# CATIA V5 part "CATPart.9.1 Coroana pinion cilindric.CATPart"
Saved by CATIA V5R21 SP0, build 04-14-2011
Part number: Coroana pinion cilindric
Bounding box of the stored display mesh (mm): x -26.905 to 26.634, y -26.886 to 26.822, z -26 to 126
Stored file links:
  C:\Users\MIRCEA\Desktop\MOM\Mogan\model\CATPart.9.1 Coroana pinion cilindric.CATPart
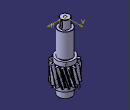
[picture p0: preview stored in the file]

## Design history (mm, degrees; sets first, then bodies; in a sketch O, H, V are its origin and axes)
Parameters
  `Date de intrare` = ""
  z1 = 15
  z2 = 49
  beta = 15 deg
  m_n = 3 mm
  aw = 100 mm
  xn1 = 0.208
  b1 = 40 mm
  b2 = 37 mm
  g = 4 mm
  `Date calculate si limita` = ""
  Ri1 = 16.1677 mm {= rf1-g}
  a = 99.3865 mm {= m_t * (z1 +z2 )/2}
  xn2 = 0.000851888 {= xsn - xn1}
  z1_min = 14
  aw_min = 98.1865 mm {= a - 0.4 * m_n}
  aw_max = 102.3865 mm {= a + m_n}
  x_min = -0.0714286 {= (-z1 + z1_min)/z1_min}
  s_an_min = 1.2 mm {= 0.4*m_n}
  epsilon_affa_min = 1.3
  `Unghiul de rotire` = ""
  ROT_1 = 0 deg
  `Alte date calculate` = ""
  u = 3.26667 {= z2 /z1}
  m_t = 3.1058 mm {= m_n / cos(beta )}
  alfat = 20.6469 deg {= atan(tan(alfa0_n )/cos(beta ))}
  alfawt = 21.5604 deg {= acos(a /aw * cos(alfat ) )}
  xsn = 0.208852 {= (tan(alfawt)-alfawt_r -tan(alfat) + alfat_r) * (z1 +z2 )/tan(alfa0_n)/2}
  aw_rec = 100 mm {= m_t * (z2 +z1 )*cos(alfat )/cos(alfawt )/2}
  rb1 = 21.7976 mm {= rd1 * cos(alfat )}
  rb2 = 71.2055 mm {= rd2 * cos(alfat )}
  rd1 = 23.2937 mm {= m_t *z1/2}
  rd2 = 76.0928 mm {= m_t *z2 /2}
  rw1 = 23.4375 mm {= aw/(u+1)}
  rw2 = 76.5625 mm {= aw-rw1}
  rf1 = 20.1677 mm {= m_n * (z1 /cos(beta )-2*(ha_n +c0_n-xn1 ))/2}
  rf2 = 72.3454 mm {= m_n * (z2 /cos(beta )-2*(ha_n +c0_n-xn2 ))/2}
  ra1 = 26.9046 mm {= (2*aw_rec  -m_n *(z2  /cos(beta )-2*(ha_n -xn2 )))/2}
  ra2 = 79.0823 mm {= (2*aw_rec  -m_n *(z1   /cos(beta )-2*(ha_n -xn1 )))/2}
  `Coordonate ale punctelor de pe evolventa 1` = ""
  Xe11 = 0.0083 mm {= rb1  *sqrt(1+(1*psi_r)  * (1*psi_r) ) * sin((1*phi) - atan((1*psi_r)))}
  Ye11 = 21.9168 mm {= rb1 *sqrt(1+(1*psi_r) * (1*psi_r) ) * cos((1*phi) - atan((1*psi_r )))}
  Xe12 = 0.0665 mm {= rb1  *sqrt(1+(2*psi_r )  * (2*psi_r)) * sin((2*phi) - atan((2*psi_r )))}
  Ye12 = 22.2704 mm {= rb1 *sqrt(1+(2*psi_r) * (2*psi_r) ) * cos((2*phi) - atan((2*psi_r )))}
  Xe13 = 0.2231 mm {= rb1  *sqrt(1+(3*psi_r)  * (3*psi_r) ) * sin((3*phi) - atan((3*psi_r)))}
  Ye13 = 22.8469 mm {= rb1 *sqrt(1+(3*psi_r) * (3*psi_r) ) * cos((3*phi) - atan((3*psi_r )))}
  Xe14 = 0.5247 mm {= rb1*sqrt(1+(4*psi_r)  * (4*psi_r) ) * sin((4*phi) - atan((4*psi_r)))}
  Ye14 = 23.6268 mm {= rb1 *sqrt(1+(4*psi_r) * (4*psi_r) ) * cos((4*phi) - atan((4*psi_r )))}
  Xe15 = 1.0147 mm {= rb1  *sqrt(1+(5*psi_r )  * (5*psi_r)) * sin((5*phi) - atan((5*psi_r )))}
  Ye15 = 24.5839 mm {= rb1 *sqrt(1+(5*psi_r) * (5*psi_r) ) * cos((5*phi) - atan((5*psi_r )))}
  Xe16 = 1.7321 mm {= rb1*sqrt(1+(6*psi_r )  * (6*psi_r)) * sin((6*phi) - atan((6*psi_r )))}
  Ye16 = 25.6848 mm {= rb1 *sqrt(1+(6*psi_r) * (6*psi_r) ) * cos((6*phi) - atan((6*psi_r )))}
  Xe17 = 2.7111 mm {= rb1  *sqrt(1+(7*psi_r )  * (7*psi_r)) * sin((7*phi) - atan((7*psi_r )))}
  Ye17 = 26.8904 mm {= rb1 *sqrt(1+(7*psi_r) * (7*psi_r) ) * cos((7*phi) - atan((7*psi_r )))}
  Xe18 = 3.9797 mm {= rb1  *sqrt(1+(8*psi_r )  * (8*psi_r)) * sin((8*phi) - atan((8*psi_r )))}
  Ye18 = 28.1561 mm {= rb1 *sqrt(1+(8*psi_r) * (8*psi_r) ) * cos((8*phi) - atan((8*psi_r )))}
  tetaC = 1.07882 {= (tan(alfawt ) - alfawt_r )*180/3.14159265}
  tetaC_g = 1.0788 deg {= tetaC *Angle}
  rho = 1.1647 mm {= rho_n *m_t}
  tau1 = 6 deg {= 360/z1 *Angle/4}
  tau2 = 1.8367 deg {= 360/z2 * Angle /4}
  Xe21 = 0.0272 mm {= Xe11 * u}
  Ye21 = 28.4052 mm {= aw_rec - Ye11 * u}
  Xe22 = 0.2171 mm {= Xe12 * u}
  Ye22 = 27.2499 mm {= aw_rec -Ye12 * u}
  Xe23 = 0.7287 mm {= Xe13 * u}
  Ye23 = 25.3669 mm {= aw_rec - Ye13 * u}
  X24 = 1.714 mm {= Xe14 * u}
  Ye24 = 22.8191 mm {= aw_rec -Ye14 * u}
  Xe25 = 3.3146 mm {= Xe15 * u}
  Ye25 = 19.6927 mm {= aw_rec -Ye15 * u}
  Xe26 = 5.6583 mm {= Xe16 * u}
  Ye26 = 16.0962 mm {= aw_rec - Ye16 * u}
  Xe27 = 8.8563 mm {= Xe17 *u}
  Ye27 = 12.1579 mm {= aw_rec -Ye17 * u}
  Xe28 = 13.0004 mm {= Xe18 * u}
  Ye28 = 8.0235 mm {= aw_rec -Ye18 * u}
  rot2 = 0 deg {= - ROT_1/u}
  pbt = 9.1306 mm {= PI * m_t * cos(alfat)}
  phi = 6 deg
  Angle = 1 deg
  alfat_r = 0.360356 {= alfat}
  alfawt_r = 0.376301 {= alfawt}
  psi_r = 0.10472 {= phi}
  `Parametri cremaliera` = ""
  alfa0_n = 20 deg
  ha_n = 1
  c0_n = 0.25
  rho_n = 0.375
  b0 = 1 mm
AxisSystem1: origin (0, 0, 0), X (1, 0, 0), Y (0, 1, 0), Z (0, 0, 1)
Sketch1 on yz-plane, origin (0, 0, 0), H (0, 1, 0), V (0, 0, 1)
  line L1 (16.168, 40) -> (16.168, 0)
  point P4 (0, 66)
  reference projected line E1 through (0, 0) direction (0, 1) from Z axis
  line L2 (16.168, 0) -> (20, 0)
  line L3 (16.168, 40) -> (20, 40)
  line L4 (15, 50) -> (20, 50)
  line L5 (20, 50) -> (20, 40)
  line L6 (20, 0) -> (20, -10)
  line L7 (20, -10) -> (15, -10)
  line L8 (15, -10) -> (15, -26)
  line L9 (15, -26) -> (0, -26)
  point P11 (0, -26)
  line L10 (15, 50) -> (15, 106)
  line L11 (15, 106) -> (10, 106)
  line L12 (10, 106) -> (10, 126)
  line L13 (10, 126) -> (0, 126)
  point P15 (0, 126)
  length L1 = 40
  distance L1 E1 = 16.168
  length L8 = 16
  length L10 = 56
  length L11 = 5
  length L12 = 20
  distance L6 O = 20
  distance L5 V = 20
  vertical: L1 V, L5 V, L6 V, L8 V, L10 V, L12 V
  coincidence: P4 V, P11 V, P15 V
  horizontal: L2 H, L3 H, L4 H, L7 H, L9 H, L11 H, L13 H
Shaft1: profile Sketch1, axis Z axis, angle 360
Set1
  Point1: type OnPlane, Support xy-plane, H 0, V 21.7976 {= rb1}, Direction (1, 0, 0)
  Point2: type OnPlane, Support xy-plane, H 0.0083 {= Xe11}, V 21.9168 {= Ye11}, Direction (1, 0, 0)
  Point3: type OnPlane, Support xy-plane, H 0.0665 {= Xe12}, V 22.2704 {= Ye12}, Direction (1, 0, 0)
  Point4: type OnPlane, Support xy-plane, H 0.2231 {= Xe13}, V 22.8469 {= Ye13}, Direction (1, 0, 0)
  Point5: type OnPlane, Support xy-plane, H 0.5247 {= Xe14}, V 23.6268 {= Ye14}, Direction (1, 0, 0)
  Point6: type OnPlane, Support xy-plane, H 1.0147 {= Xe15}, V 24.5839 {= Ye15}, Direction (1, 0, 0)
  Point7: type OnPlane, Support xy-plane, H 1.7321 {= Xe16}, V 25.6848 {= Ye16}, Direction (1, 0, 0)
  Point8: type OnPlane, Support xy-plane, H 2.7111 {= Xe17}, V 26.8904 {= Ye17}, Direction (1, 0, 0)
  Point9: type OnPlane, Support xy-plane, H 3.9797 {= Xe18}, V 28.1561 {= Ye18}, Direction (1, 0, 0)
  Circle1: type CtrRad, Start 60, End 120, Center vertex [YZ plane of AxisSystem1 | ZX plane of AxisSystem1 | XY plane of AxisSystem1], Support xy-plane, Radius 20.1677 {= rf1}, FirstDirection (1, 0, 0)
  Circle2: type CtrRad, Start 60, End 120, Center vertex [YZ plane of AxisSystem1 | ZX plane of AxisSystem1 | XY plane of AxisSystem1], Support xy-plane, Radius 26.9046 {= ra1}, FirstDirection (1, 0, 0)
  Line1: type Angle, RefPoint vertex [YZ plane of AxisSystem1 | ZX plane of AxisSystem1 | XY plane of AxisSystem1], Curve Y axis, Support xy-plane, Start 0, End 30.2677 {= ra1 + ra1 /8}, Angle -7.0788 {= -tetaC_g - tau1}
  Line2: type Angle, RefPoint vertex of Line1, Curve Y axis, Support xy-plane, Start 0, End 22.1845 {= rf1 +rf1 /10}, Angle 4.9212 {= -tetaC_g + tau1}
  Point10: type OnPlane, Support xy-plane, H 0, V 21.5796 {= rb1 - rb1 /100}, Direction (1, 0, 0)
  Point11: type OnPlane, Support xy-plane, H 0, V 21.3616 {= rb1 - 1/50 * rb1}, Direction (1, 0, 0)
  Point12: type OnPlane, Support xy-plane, H 0, V 20.7077 {= rb1 - rb1 /20}, Direction (1, 0, 0)
  Point13: type OnPlane, Support xy-plane, H 0, V 19.6178 {= rb1 - rb1 /10}, Direction (1, 0, 0)
  Point14: type OnPlane, Support xy-plane, H 0, V 17.4381 {= rb1 -rb1 /5}, Direction (1, 0, 0)
  Point15: type OnPlane, Support xy-plane, H 0, V 14.5317 {= rb1 - rb1 /3}, Direction (1, 0, 0)
  Curve1: Elements (Point15; Point14; Point13; Point12; Point11; Point10; Point1; Point2; Point3; Point4; Point5; Point6; Point7; Point8; Point9)
  Trim1: Trimmed (Circle2; Curve1)
  Trim2: Trimmed (Line1; Trim1)
  Circle3: type CtrRad, Start 80, End 100, Center vertex [YZ plane of AxisSystem1 | ZX plane of AxisSystem1 | XY plane of AxisSystem1], Support xy-plane, Radius 16.1677 {= rf1 - g}, FirstDirection (1, 0, 0)
  Corner1: Element1 Circle1, Element2 Trim2, Radius 1.125
  Trim3: Trimmed (Circle1; Corner1)
  Trim4: Trimmed (Trim2; Trim3)
  Trim5: Trimmed (Trim4; Line2)
  Trim6: Trimmed (Trim5; Circle3)
  Point16: type OnPlane, Support xy-plane, H 0, V 100 {= aw_rec}, Direction (1, 0, 0)
  Circle4: type CtrRad, Start -80, End -100, Center Point16, Support xy-plane, Radius 72.3454 {= rf2}, FirstDirection (1, 0, 0)
  Circle5: type CtrRad, Start -80, End -100, Center Point16, Support xy-plane, Radius 79.0823 {= ra2}, FirstDirection (1, 0, 0)
  Point17: type OnPlane, Support xy-plane, H -0.0272 {= -Xe21}, V 28.4052 {= Ye21}, Direction (1, 0, 0)
  Point18: type OnPlane, Support xy-plane, H -0.2171 {= -Xe22}, V 27.2499 {= Ye22}, Direction (1, 0, 0)
  Point19: type OnPlane, Support xy-plane, H -0.7287 {= -Xe23}, V 25.3669 {= Ye23}, Direction (1, 0, 0)
  Point20: type OnPlane, Support xy-plane, H -1.714 {= -X24}, V 22.8191 {= Ye24}, Direction (1, 0, 0)
  Point21: type OnPlane, Support xy-plane, H -1.714 {= -X24}, V 22.8191 {= Ye24}, Direction (1, 0, 0)
  Point22: type OnPlane, Support xy-plane, H -3.3146 {= -Xe25}, V 19.6927 {= Ye25}, Direction (1, 0, 0)
  Point23: type OnPlane, Support xy-plane, H -5.6583 {= -Xe26}, V 16.0962 {= Ye26}, Direction (1, 0, 0)
  Point24: type OnPlane, Support xy-plane, H -8.8563 {= -Xe27}, V 12.1579 {= Ye27}, Direction (1, 0, 0)
  Point25: type OnPlane, Support xy-plane, H -13.0004 {= -Xe28}, V 8.0235 {= Ye28}, Direction (1, 0, 0)
  Point26: type OnPlane, Support xy-plane, H 0, V 28.7945 {= aw_rec - rb2}, Direction (1, 0, 0)
  Point27: type OnPlane, Support xy-plane, H 0, V 29.5066 {= aw_rec - rb2 +rb2 /100}, Direction (1, 0, 0)
  Point28: type OnPlane, Support xy-plane, H 0, V 30.2187 {= aw_rec - rb2 + rb2/50}, Direction (1, 0, 0)
  Point29: type OnPlane, Support xy-plane, RefPoint vertex [YZ plane of AxisSystem1 | ZX plane of AxisSystem1 | XY plane of AxisSystem1], H 0, V 32.3548 {= aw_rec - rb2 +rb2 /20}, Direction (1, 0, 0)
  Point30: type OnPlane, Support xy-plane, H 0, V 35.9151 {= aw_rec - rb2 +rb2 /10}, Direction (1, 0, 0)
  Circle6: type CtrRad, Start -80, End -100, Center Point16, Support xy-plane, Radius 68.3454 {= rf2 - g}, FirstDirection (1, 0, 0)
  Line3: type Angle, RefPoint Point16, Curve Y axis, Support xy-plane, Start 0, End 83.0823 {= ra2 + g}, Angle 177.0844 {= Angle *180-tau2 - tetaC_g}
  Line4: type Angle, RefPoint Point16, Curve Y axis, Support xy-plane, Start 0, End 83.0823 {= ra2 + g}, Angle 180.7579 {= Angle *180 + tau2 -tetaC_g}
  Point31: type OnPlane, Support xy-plane, H 0, V 43.0356 {= aw_rec - rb2 +rb2 /5}, Direction (1, 0, 0)
  Curve2: Elements (Point25; Point24; Point23; Point22; Point21; Point19; Point18; Point17; Point26; Point27; Point28; Point29; Point30; Point31)
  Corner2: Element1 Curve2, Element2 Circle4, Support xy-plane, Radius 1.1647 {= rho}
  Trim7: Trimmed (Line3; Circle5)
  Trim8: Trimmed (Trim7; Curve2)
  Trim9: Trimmed (Line4; Circle6)
  Trim10: Trimmed (Circle4; Corner2)
  Trim11: Trimmed (Trim8; Trim10)
  Trim12: Trimmed (Trim11; Trim9)
  Rotate1: ToTransfor Trim6, Axis Z axis, Angle 1.0788 {= tetaC_g}
  Line5: type PtDir, RefPoint Point16, Direction (0, 0, 1), Start 0, End 46.4066
  Rotate2: ToTransfor Rotate1, Axis Z axis, Angle 0 {= ROT_1}
  Symmetry1: ToTransfor Rotate2, Reference {plane type 2Lines, Element1 edge of Rotate2, Element2 Z axis}
  Translate1: ToTransfor Rotate2, Direction Z axis, Length 40 {= b1}
  Translate2: ToTransfor Symmetry1, Direction Z axis, Length 40 {= b1}
  Rotate3: ToTransfor Translate1, Axis Z axis, Angle -26.3631 {= -b1/rb1*tan(beta)*cos(alfat)}
  Rotate4: ToTransfor Translate2, Axis Z axis, Angle -26.3631 {= -b1/rb1*tan(beta)*cos(alfat)}
  Loft1: Sections (Rotate2; Rotate3)
  Loft2: Sections (Symmetry1; Rotate4)
  CircPattern1: of Loft1, instances 15 {= z1}, angular step 24 {= 360.0*1 deg/CircPattern1.AngularNumber}, axis from Z axis
  CircPattern2: of Loft2, instances 15 {= z1}, angular step 24 {= 360.0*1 deg/CircPattern2.AngularNumber}, axis from Z axis
  Add1: tool CircPattern2
  Plane1: type Offset, RefPlane yz-plane, Offset 6.5
Body1 (main body)
  Sketch2 on yz-plane, origin (0, 0, 0), H (0, 1, 0), V (0, 0, 1)
    line L1 (15.2774, -10.0047) -> (14.9151, -9.9701)
    arc A1 centre (14.9072, -10.0521) radius 0.0824 from (14.9151, -9.9701) to (14.8259, -10.0653) ccw
    line L2 (14.8259, -10.0653) -> (14.8432, -10.1721)
    arc A2 centre (14.9493, -10.1549) radius 0.1076 from (14.8432, -10.1721) to (14.8892, -10.2441) ccw
    tangency: A1 L1, L2 A1, A2 L2
  Groove1: profile Sketch2, axis Z axis, angle 360
  Sketch3 on yz-plane, origin (0, 0, 0), H (0, 1, 0), V (0, 0, 1)
    line L1 (15.1715, 49.9993) -> (15.0102, 49.9334)
    arc A1 centre (14.9641, 50.0462) radius 0.1219 from (15.0102, 49.9334) to (14.8428, 50.0592) cw
    line L2 (14.8428, 50.0592) -> (14.9086, 50.233)
    tangency: A1 L1
  Groove2: profile Sketch3, axis Z axis, angle 360
  Sketch4 on Plane1, origin (6.5, 0, 0), H (0, 1, 0), V (0, 0, 1)
    construction line L1 (0, 122) -> (0, 110.064)
    point P1 (0, 122)
    line L2 (3, 122) -> (3, 110.064)
    line L3 (-3, 110.064) -> (-3, 122)
    arc A1 centre (0, 110.064) radius 3 from (3, 110.064) to (-3, 110.064) cw
    arc A2 centre (0, 122) radius 3 from (-3, 122) to (3, 122) cw
    point P3 (3, 122)
    point P4 (3, 110.064)
    reference projected line E1 (-10, 126) -> (10, 126) from edge [face of Shaft1 from Sketch1.L12 | face of Shaft1 from Sketch1.L13]
    distance L1 L2 = 3
    distance P3 P4 = 11.936
    distance A2 E1 = 1
    coincidence: P1 V
    vertical: L1 V
    tangency: A1 L2, A2 L2, A1 L3, A2 L3
  Pocket1: profile Sketch4, direction (1, 0, 0), length 20
  Add2: tool Add1
  Chamfer1: length 0.5, angle 45, on edge [face of Shaft1 from Sketch1.L7 | face of Shaft1 from Sketch1.L6]; edge [face of Shaft1 from Sketch1.L9 | face of Shaft1 from Sketch1.L8]
  Sketch5 on face of Shaft1 from Sketch1.L9, origin (0, 0, -26), H (1, 0, 0), V (0, -1, 0)
    point P1 (0, 0)
    reference projected point E1 (0, 0) from Sketch9.P1
    coincidence: E1 P1
  Hole1: placed by Sketch5, at (0, 0, -26) direction (0, 0, 1), diameter 5, depth 4, V-bottom angle 100, countersink depth 2, countersink angle 50
  Sketch6 on face of Shaft1 from Sketch1.L13, origin (0, 0, 126), H (1, 0, 0), V (0, 1, 0)
    point P1 (0, 0)
    reference projected point E1 (0, 0) from Sketch8.P1
    coincidence: E1 P1
  Hole2: placed by Sketch6, at (0, 0, 126) direction (0, 0, -1), diameter 5, depth 4, V-bottom angle 100, countersink depth 2, countersink angle 50
  Chamfer2: length 0.5, angle 45, on edge [face of Shaft1 from Sketch1.L12 | face of Shaft1 from Sketch1.L13]; edge [face of Shaft1 from Sketch1.L10 | face of Shaft1 from Sketch1.L11]
  Sketch7 on face of Shaft1 from Sketch1.L13, origin (0, 0, 126), H (1, 0, 0), V (0, 1, 0)
  Sketch8 on face of Shaft1 from Sketch1.L13, origin (0, 0, 126), H (1, 0, 0), V (0, 1, 0)
    point P1 (0, 0)
    coincidence: P1 O
  Sketch9 on face of Shaft1 from Sketch1.L9, origin (0, 0, -26), H (1, 0, 0), V (0, -1, 0)
    point P1 (0, 0)
    coincidence: P1 O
